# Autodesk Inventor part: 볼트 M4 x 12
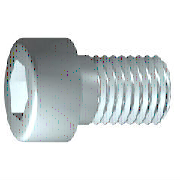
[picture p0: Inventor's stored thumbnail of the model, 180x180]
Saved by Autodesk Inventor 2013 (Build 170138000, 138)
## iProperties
IsCustomPart: 0
Created: 2016-05
Part Number: 볼트 M4 x 12
Material: 강, 연강
Description: 6각머리 태핑 나사
Document SubType Name: Modeling
Standard: KS B 1003
Designer: mduedu
Standards Organization: KS
Language: ko-KR
Size Designation: M 4 x 12
Categories: <MemberInstance><Categories><Category DisplayName="조임쇠" InternalName="e4da775c-781d-43d5-af7c-5136215cf5a6" Mnemonic="FSTN"><Category DisplayName="볼트" InternalN
Density: 1 g/cm^3
Author: mduedu
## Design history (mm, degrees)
sketch "스케치1"
  geometry: L1 (-1, 0)-(12, 0); L2 (12, 0)-(12, 2); L3 (12, 2)-(1.75, 2); L4 (1.75, 2)-(1.32, 2); L5 (1.32, 2)-(0, 2); L6 (0, 2)-(0, 3.5); L7 (0, 3.5)-(-4, 3.5); L8 (-4, 3.5)-(-4, 1.732); L9 (-4, 1.732)-(-2, 1.732); L10 (-2, 1.732)-(-1, 0); L11 (-7.2, 0)-(15.2, 0) reference; L12 (0, -0.7)-(0, 4.2) reference; L13 (1.75, 2)-(0, 2)
  constraints: 22 end point, 6 parallel, 2 collinear, 2 perpendicular, 1 horizontal, 1 point on line
  dimensions: "d1" = 10.25 distance from line of L3.end L2 (= GEL); "d2" = 0.42952 distance of L4.end L3.end (computed from GAL); "d3" = 4 distance between parallel lines of L8 L6 (= KOH); "d4" = 2 distance of L8.end L9.end (= INTI); "d5" = 60 deg angle of L10 L1; "d6" = 4 diameter of L3 L1 (= GD); "d7" = 4 diameter of L5 L1 (= BDM); "d8" = 3.4641 diameter of L9 L1 (= 1.1547 x SW); "d9" = 7 diameter of L7 L1 (= KOD); "d26" = 12 distance between parallel lines of L12 L2 (= NLG)
revolve "본체" sketch "스케치1" stored, may be unused: angle "d10" = 90 deg
sketch "스케치2"
  geometry: L1 (0, -4.9)-(0, 4.9) reference; L2 (-4.9, 0)-(4.9, 0) reference; L3 (1.732, 0)-(0.866, -1.5); L4 (0.866, -1.5)-(-0.866, -1.5); L5 (-0.866, -1.5)-(-1.732, 0); L6 (-1.732, 0)-(-0.866, 1.5); L7 (-0.866, 1.5)-(0.866, 1.5); L8 (0.866, 1.5)-(1.732, 0); 2 further points
  constraints: 12 end point, 1 coincident, 1 horizontal alignment, 1 point on line, 12 other
extrude "슬롯" join sketch "스케치2" stored distance "d11" = 10; taper "d12" = 0 deg
workplane "Work Plane1"
fillet "Fillet2" dims "d30" = 0.1 (= R)
body "Solid1"
fillet "모깎기1" dims "d17" = 0.4 (= RR)
feature "스레드" dims "d13" = 10.25 (= GEL), "d14" = 0
chamfer "모따기1" distance "d15" = 0.42941 (= -0.5 x SPD + 0.5 x GD); stored, may be unused: second distance "d16" = 0.42941 (= GUL), angle "d27" = 45 deg
other parameters: "GD" = 4 (= NND) [user parameter; used in 2 equation terms], "NLG" = 12 [user parameter; used in 1 equation term], "GEL" = 10.25 [user parameter; used in 2 equation terms], "KOD" = 7 [user parameter; used in 1 equation term], "KOH" = 4 [user parameter; used in 1 equation term], "INTI" = 2 [user parameter; used in 1 equation term], "GAL" = 0.42941 (= 0.61345 x PTC) [user parameter; used in 1 equation term], "GUL" = 0.42941 (= 0.61345 x PTC) [user parameter; used in 1 equation term], "BDM" = 4 (= NND) [user parameter; used in 1 equation term], "SW" = 3 [user parameter; used in 2 equation terms], "RR" = 0.4 [user parameter; used in 1 equation term], "SPD" = 3.14117 (= NND - 1.2269 x PTC) [user parameter; used in 1 equation term], "d19" = 0, "d28" = 0, "d29" = 0, "R" = 0.1 [user parameter; used in 1 equation term], "PHH" = 0.2 [user parameter], "GD1" = 3.14117 (= THREADDIA - 1.2269 x PTC) [user parameter], "THREADDIA" = 4 [user parameter; used in 1 equation term], "FAWI" = 45 deg [user parameter], "TPU" = 14.28571 (computed from PTC) [user parameter], "PTC" = 0.7 [user parameter; used in 5 equation terms], "NND" = 4 [user parameter; used in 3 equation terms], "TOA" = 30 deg [user parameter], "E0" = 3.465 (= 1.155 x SW) [user parameter]
